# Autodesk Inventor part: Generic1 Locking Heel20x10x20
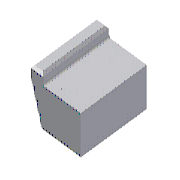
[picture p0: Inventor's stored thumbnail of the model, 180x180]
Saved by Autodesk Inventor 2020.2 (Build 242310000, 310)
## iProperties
Manager: www.cadconsulting.pl
Company: Fabian Stasiak CAD Consulting
Created: 2014-02
Part Number: Generic1 Locking Heel20x10x20
Material: DIN 1.2162
Description: Pięta blokująca
Document SubType Name: Modeling
Designer: F.Stasiak
Standard Revision: 1
Manufacturer: Generic
Language: pl-PL
Size Designation: 20x10x20
Categories: <MemberInstance><Categories><Category DisplayName="Forma wtryskowa" InternalName="349578f2-f4d4-4954-8c09-8e99297a61c0" Mnemonic="MOLD"><Category DisplayName="K
Density: 7.85 g/cm^3
Appearance: Domyślna
Catalog Web Link: www.expertbooks.pl
IsCustomPart: 1
Author: F.Stasiak
Subject: Zbiór ćwiczeń. Autodesk Inventor 2020. Kurs Professional
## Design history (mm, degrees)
feature "Powierzchnia zszycia1" dims "d126" = 0.254 (derived)
node "LH_SL"
body "Solid1"
sketch "Sketch1"
  geometry: L1 (20, 0)-(20, 4); L2 (20, 4)-(14, 4); L3 (14, 4)-(14, 0); L4 (14, 0)-(0, 0); L5 (0, 0)-(0, -10); L6 (0, -10)-(16.36, -10); L7 (16.36, -10)-(20, 0); 2 further points
  constraints: 14 end point, 4 parallel, 1 coincident, 1 horizontal alignment, 1 midpoint, 1 perpendicular, 1 vertical
  dimensions: "d0" = 6 distance between parallel lines of L1 L3 (= LH_l_); "d3" = 20 distance between parallel lines of L1 L5 (= LH_L); "d4" = 10 distance between parallel lines of L4 L6 (= LH_T); "d5" = 4 distance from line of L1.start L2 (= LH_H); "d6" = 20 deg angle of L1 L7 (= LH_ang - X_ang)
extrude "Wyciągnięcie proste1" new body sketch "Sketch1" stored distance "d7" = 30 (= LH_A); taper "d8" = 0 deg
sketch "Sketch2"
  geometry: L1 (-14, 0)-(0, 0) reference; L2 (0, 0)-(0, -10) reference; L3 (0, -10)-(-16.36, -10) reference; L4 (-16.36, -10)-(-20, 0) reference; L5 (-20, 5)-(-14, 5); L6 (-20, 4)-(-14, 4) reference; L7 (-20, 5)-(-20, 0); L8 (-14, 5)-(-14, 0)
  constraints: 6 end point, 1 parallel, 1 perpendicular
  dimensions: "d110" = 1 distance between parallel lines of L6 L5 (= LH_esh)
body "Srf1"
body "Srf2"
body "Srf3"
body "Srf4"
feature "WyciągnięcieProstePow1" dims "d62" = 30 (= LH_A), "d63" = 0
feature "Zamknięcie obwiedni1" dims "d77" = 0, "d111" = 0, "d112" = 0, "d113" = 0, "d114" = 0, "d115" = 0, "d116" = 0, "d117" = 0
feature "Zamknięcie obwiedni2" dims "d118" = 0, "d119" = 0, "d120" = 0, "d121" = 0, "d122" = 0, "d123" = 0, "d124" = 0, "d125" = 0
other parameters: "LH_L" = 20 [user parameter; used in 1 equation term], "LH_T" = 10 [user parameter; used in 1 equation term], "LH_A" = 30 [user parameter; used in 2 equation terms], "LH_ang" = 20 deg [user parameter; used in 1 equation term], "LH_l_" = 6 [user parameter; used in 1 equation term], "LH_H" = 4 [user parameter; used in 1 equation term], "d95" = 0, "LH_esh" = 1 [user parameter; used in 1 equation term], "X_ang" = 0 deg [user parameter; used in 1 equation term]
